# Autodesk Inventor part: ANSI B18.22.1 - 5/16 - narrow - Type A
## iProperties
Comments: To add or edit properties for Autodesk Inventor files, use iProperties.
Created: 2005-06
Part Number: ANSI B18.22.1 - 5/16 - narrow - Type A
Vendor: Autodesk Inc.
Document SubType Name: Modeling
Designer: John Blackburn
Material: Default
Description: Washer A
Standard: ANSI B18.22.1
Size Designation: 5/16 - narrow - Type A
Alert: To add or edit properties for Autodesk Inventor files, use iProperties.
Control State: 0
Master: False
Checked Out: False
Shininess: 64.0
Length Units: 11272
Angle Units: 11279
Time Units: 11290
Mass Units: 11286
Length Display Precision: 3
Angle Display Precision: 2
Compacted: True
Classification: un/spsc 31161807
Density: 0.0
Volumn: 0.0
Area: 0.0
PropertySet Name: Model Information
Author: John Blackburn
Revision Number: 8
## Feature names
1. Body [Extrusion]
